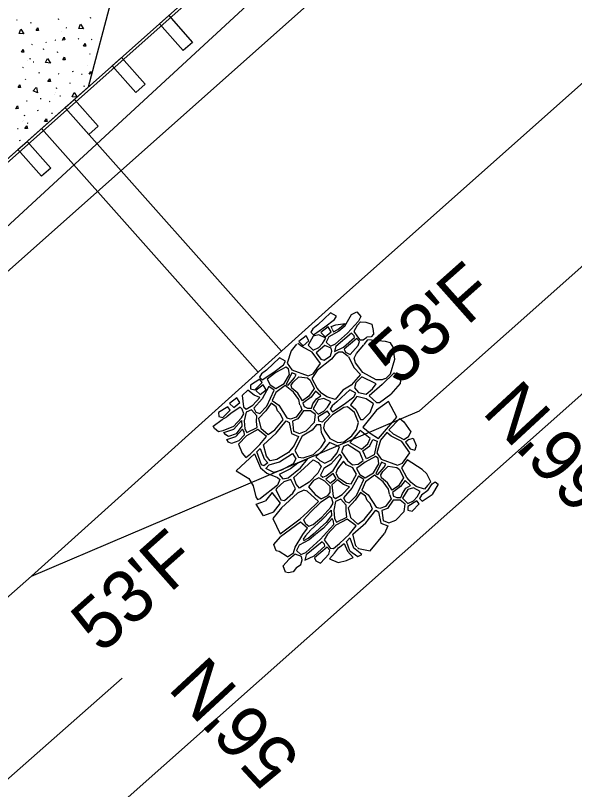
# Model space of a CAD drawing. Extents: x 49683 to 58852, y 49525 to 54803.
# Drawn here: x 53957.6 to 54010.8, y 51788.8 to 51862.4 of the extents above; entities that cross this region are included whole.
import ezdxf

# ---------------------------------------------------------------- set-up
doc = ezdxf.new("R2010")
doc.units = 0
for name, color, linetype in [('Level 11', 7, 'Continuous'), ('Level 13', 7, 'Continuous'), ('Level 16', 7, 'Continuous'), ('Level 18', 7, 'Continuous'), ('Level 27', 7, 'Continuous'), ('Level 33', 7, 'Continuous'), ('Level 48', 7, 'Continuous'), ('Level 61', 7, 'Continuous'), ('Level 8', 7, 'Continuous')]:
    doc.layers.add(name, color=color, linetype=linetype)

msp = doc.modelspace()

# ---------------------------------------------------------------- linework, layer by layer
at = {"layer": 'Level 11'}
msp.add_line((53944.235, 51830.768), (54450.301, 52297.6), dxfattribs=at)
at = {"layer": 'Level 13'}
msp.add_line((53681.554, 51593.39), (53996.93, 51873.722), dxfattribs=at)
at = {"layer": 'Level 16'}
for points in [[(53988.147, 51833.841), (53987.57, 51834.165), (53986.351, 51833.009), (53985.878, 51832.641), (53985.689, 51832.326), (53985.941, 51832.074), (53987.033, 51832.81), (53987.958, 51833.504)], [(53987.356, 51832.81), (53986.662, 51832.273), (53987.075, 51831.883), (53987.623, 51832.341)], [(53985.24, 51831.957), (53984.547, 51831.42), (53984.959, 51831.029), (53985.507, 51831.488)], [(53987.121, 51831.744), (53986.46, 51832.069), (53985.925, 51831.932), (53985.441, 51831.091), (53985.923, 51830.588), (53986.459, 51830.851), (53986.806, 51831.24)], [(53989.577, 51832.213), (53988.08, 51830.962), (53987.945, 51830.459), (53988.815, 51830.889), (53989.833, 51831.809), (53989.821, 51831.968)], [(53990.078, 51831.711), (53988.876, 51830.681), (53988.999, 51830.411), (53989.427, 51830.179), (53990.212, 51831.037), (53990.323, 51831.417)], [(53986.193, 51830.347), (53986.633, 51829.735), (53986.952, 51829.637), (53987.565, 51830.054), (53987.688, 51830.496), (53987.627, 51830.802), (53987.039, 51831.046)], [(53983.284, 51829.542), (53982.707, 51829.866), (53981.488, 51828.71), (53981.015, 51828.342), (53980.826, 51828.027), (53981.078, 51827.776), (53982.17, 51828.512), (53983.095, 51829.206)], [(53983.324, 51828.996), (53982.356, 51828.468), (53981.534, 51827.842), (53981.84, 51827.291), (53982.367, 51826.961), (53983.151, 51827.427), (53983.654, 51828.298), (53983.582, 51828.837)], [(53983.9, 51828.445), (53983.359, 51827.342), (53983.543, 51827.281), (53984.144, 51827.98), (53984.316, 51828.274)], [(53986.005, 51826.953), (53985.514, 51826.217), (53984.914, 51825.788), (53984.473, 51826.498), (53983.898, 51826.975), (53983.837, 51827.257), (53984.021, 51827.563), (53984.549, 51828.066), (53985.369, 51827.957), (53985.626, 51827.749)], [(53991.901, 51827.402), (53990.558, 51828.072), (53989.99, 51827.483), (53989.864, 51827.021), (53990.231, 51826.57), (53990.965, 51826.403), (53991.575, 51826.929)], [(53980.837, 51827.828), (53979.955, 51827.281), (53979.975, 51826.924), (53980.363, 51826.83), (53981.057, 51827.523)], [(53981.166, 51827.31), (53980.473, 51826.773), (53980.886, 51826.383), (53981.434, 51826.841)], [(53979.719, 51826.78), (53979.171, 51826.298), (53979.304, 51825.204), (53979.539, 51824.992), (53980.176, 51825.383), (53980.847, 51826.099), (53980.3, 51826.333)], [(53981.708, 51827.139), (53981.081, 51825.977), (53980.287, 51825.071), (53980.477, 51824.702), (53980.834, 51824.591), (53981.527, 51825.285), (53982.222, 51826.805)], [(53986.147, 51826.702), (53985.716, 51826.145), (53984.939, 51825.557), (53985.054, 51825.231), (53985.369, 51825.085), (53985.757, 51825.096), (53985.894, 51825.484), (53986.23, 51825.968), (53986.651, 51826.241)], [(53989.979, 51826.507), (53989.402, 51826.832), (53988.183, 51825.676), (53987.71, 51825.308), (53987.521, 51824.993), (53987.772, 51824.741), (53988.865, 51825.477), (53989.789, 51826.171)], [(53978.672, 51826.078), (53977.978, 51825.541), (53978.391, 51825.15), (53978.939, 51825.609)], [(53987.595, 51825.675), (53986.934, 51826), (53986.398, 51825.863), (53985.914, 51825.023), (53986.397, 51824.519), (53986.932, 51824.782), (53987.279, 51825.171)], [(53991.646, 51825.491), (53990.965, 51825.984), (53990.073, 51826.182), (53989.473, 51825.415), (53989.977, 51824.954), (53990.427, 51823.999), (53990.658, 51823.999), (53991.341, 51824.682)], [(53977.805, 51825.204), (53976.923, 51824.657), (53976.944, 51824.3), (53977.332, 51824.206), (53978.026, 51824.9)], [(53981.919, 51825.564), (53981.404, 51824.826), (53980.733, 51824.11), (53980.944, 51823.183), (53981.647, 51822.57), (53982.262, 51823.006), (53983.057, 51823.979), (53982.823, 51824.526), (53982.533, 51824.816), (53982.388, 51825.207)], [(53989.179, 51825.205), (53988.833, 51825.131), (53987.761, 51824.437), (53986.984, 51823.659), (53986.889, 51823.208), (53987.014, 51822.893), (53987.496, 51822.201), (53988.262, 51821.813), (53988.829, 51821.877), (53989.586, 51822.465), (53990.038, 51823.043), (53990.238, 51823.705), (53989.861, 51824.67)], [(53993.079, 51825.717), (53991.939, 51824.895), (53990.651, 51823.289), (53991.324, 51822.689), (53992.144, 51822.188), (53993.886, 51824.223)], [(53980.052, 51824.925), (53979.538, 51824.701), (53979.358, 51823.874), (53979.436, 51823.103), (53979.625, 51822.757), (53980.598, 51823.239), (53980.531, 51823.82), (53980.554, 51824.356)], [(53985.014, 51824.833), (53984.476, 51824.063), (53983.949, 51823.851), (53984.053, 51822.903), (53984.611, 51822.682), (53985.254, 51822.925), (53986.046, 51823.759), (53986.141, 51824.465), (53985.678, 51824.844)], [(53987.279, 51824.793), (53986.396, 51824.246), (53986.417, 51823.889), (53986.805, 51823.795), (53987.499, 51824.489)], [(53983.359, 51823.893), (53983.632, 51823.724), (53983.852, 51822.66), (53984.516, 51822.398), (53984.125, 51821.544), (53983.587, 51820.879), (53982.469, 51820.203), (53981.826, 51820.086), (53981.468, 51820.508), (53981.185, 51821.593), (53982.398, 51822.701)], [(53986.225, 51823.496), (53985.824, 51822.989), (53984.885, 51822.409), (53984.177, 51821.069), (53984.524, 51820.427), (53984.956, 51820.354), (53985.937, 51820.681), (53986.675, 51821.357), (53987.098, 51822.011), (53986.698, 51822.748), (53986.657, 51823.507)], [(53990.381, 51822.97), (53989.412, 51821.805), (53990.514, 51821.193), (53991.102, 51821.684), (53991.348, 51822.199)], [(53991.58, 51822.089), (53992.009, 51821.93), (53991.726, 51820.643), (53990.978, 51820.263), (53990.648, 51821.034), (53991.298, 51821.513)], [(53995.12, 51820.831), (53994.349, 51821.896), (53993.345, 51822.434), (53992.929, 51822.752), (53992.328, 51822.029), (53991.971, 51820.84), (53992.399, 51820.215), (53993.942, 51819.654), (53994.42, 51819.838)], [(53987.456, 51821.821), (53986.865, 51821.083), (53986.158, 51820.46), (53986.558, 51820.102), (53987.042, 51819.85), (53987.654, 51820.167), (53988.203, 51820.842), (53988.425, 51821.401)], [(53990.684, 51820.115), (53990.366, 51820.875), (53989.203, 51821.596), (53988.811, 51821.449), (53988.614, 51820.934), (53989.189, 51820.089), (53989.666, 51819.685), (53990.206, 51819.76)], [(53980.879, 51821.245), (53981.257, 51820.254), (53981.594, 51819.875), (53981.225, 51819.612), (53981.014, 51819.696), (53980.573, 51820.918)], [(53983.956, 51820.785), (53984.261, 51820.247), (53984.028, 51819.783), (53982.911, 51819.171), (53982.183, 51818.97), (53981.425, 51819.327), (53981.72, 51819.686), (53982.722, 51819.972)], [(53988.446, 51820.715), (53987.607, 51819.764), (53986.925, 51819.328), (53986.611, 51818.702), (53986.846, 51818.512), (53987.17, 51818.636), (53987.83, 51819.139), (53988.647, 51820.447)], [(53985.367, 51820.217), (53984.46, 51819.858), (53983.754, 51819.319), (53982.689, 51818.76), (53983.047, 51818.36), (53983.531, 51818.444), (53984.713, 51819.394)], [(53985.905, 51820.165), (53986.4, 51819.902), (53986.694, 51819.544), (53986.356, 51818.911), (53985.533, 51818.046), (53984.626, 51817.476), (53984.3, 51817.866), (53984.09, 51818.477), (53985.061, 51819.384)], [(53990.045, 51818.791), (53989.691, 51819.391), (53989.078, 51819.685), (53988.809, 51820.028), (53988.22, 51819.316), (53988.085, 51818.887), (53988.305, 51818.471), (53989.076, 51817.945), (53989.517, 51817.872)], [(53991.836, 51820.484), (53990.867, 51819.956), (53990.046, 51819.331), (53990.352, 51818.78), (53990.878, 51818.449), (53991.663, 51818.916), (53992.166, 51819.786), (53992.093, 51820.325)], [(53992.411, 51819.934), (53991.871, 51818.83), (53992.055, 51818.769), (53992.656, 51819.468), (53992.828, 51819.763)], [(53994.517, 51818.441), (53994.026, 51817.706), (53993.425, 51817.276), (53992.985, 51817.986), (53992.409, 51818.463), (53992.349, 51818.745), (53992.533, 51819.052), (53993.06, 51819.555), (53993.881, 51819.445), (53994.138, 51819.237)], [(53987.548, 51817.049), (53987.526, 51817.63), (53987.024, 51818.133), (53986.466, 51818.467), (53985.94, 51818.187), (53985.47, 51817.583), (53986.095, 51816.869), (53986.676, 51816.445), (53987.313, 51816.77)], [(53987.829, 51818.871), (53987.136, 51818.334), (53987.549, 51817.943), (53988.097, 51818.402)], [(53990.22, 51818.628), (53989.593, 51817.465), (53988.799, 51816.559), (53988.988, 51816.191), (53989.345, 51816.08), (53990.039, 51816.773), (53990.733, 51818.293)], [(53983.784, 51818.297), (53983.131, 51818.086), (53982.466, 51817.484), (53982.381, 51817.337), (53982.844, 51816.367), (53983.181, 51816.284), (53983.994, 51816.991), (53984.236, 51817.423)], [(53988.231, 51818.268), (53987.683, 51817.787), (53987.816, 51816.692), (53988.05, 51816.48), (53988.687, 51816.872), (53989.358, 51817.588), (53988.811, 51817.822)], [(53994.659, 51818.191), (53994.228, 51817.634), (53993.45, 51817.045), (53993.565, 51816.72), (53993.88, 51816.573), (53994.269, 51816.584), (53994.405, 51816.973), (53994.742, 51817.456), (53995.162, 51817.73)], [(53990.43, 51817.053), (53989.916, 51816.315), (53989.244, 51815.599), (53989.456, 51814.672), (53990.159, 51814.058), (53990.774, 51814.495), (53991.568, 51815.468), (53991.334, 51816.015), (53991.044, 51816.305), (53990.899, 51816.696)], [(53996.106, 51817.164), (53995.445, 51817.488), (53994.91, 51817.351), (53994.426, 51816.511), (53994.908, 51816.008), (53995.444, 51816.271), (53995.791, 51816.66)], [(53987.48, 51816.67), (53986.597, 51816.076), (53985.691, 51815.215), (53984.986, 51814.443), (53985.198, 51814.097), (53985.5, 51813.841), (53985.913, 51814.009), (53986.752, 51814.714), (53987.602, 51815.653), (53987.826, 51816.033), (53987.681, 51816.491)], [(53988.564, 51816.414), (53988.05, 51816.19), (53987.87, 51815.363), (53987.947, 51814.592), (53988.137, 51814.246), (53989.109, 51814.727), (53989.043, 51815.308), (53989.066, 51815.845)], [(53993.526, 51816.321), (53992.987, 51815.551), (53992.46, 51815.34), (53992.564, 51814.391), (53993.123, 51814.171), (53993.766, 51814.414), (53994.557, 51815.247), (53994.653, 51815.954), (53994.19, 51816.332)], [(53995.79, 51816.282), (53994.908, 51815.735), (53994.929, 51815.378), (53995.317, 51815.284), (53996.01, 51815.977)], [(53989.991, 51813.89), (53989.165, 51814.537), (53988.081, 51813.944), (53987.275, 51813.094), (53986.973, 51812.546), (53987.33, 51812.033), (53987.542, 51811.754), (53987.855, 51811.732), (53988.436, 51812.202), (53989.364, 51813.108)], [(53986.759, 51812.372), (53985.263, 51811.121), (53985.128, 51810.619), (53985.998, 51811.048), (53987.016, 51811.968), (53987.004, 51812.128)]]:
    msp.add_lwpolyline(points, close=True, dxfattribs=at)
for points in [[(53988.938, 51832.881), (53989.572, 51833.997), (53990.08, 51834.244), (53990.463, 51833.819), (53990.243, 51833.346), (53989.182, 51832.231)], [(53987.738, 51832.625), (53987.689, 51832.721), (53987.632, 51832.84), (53988.06, 51832.997), (53988.963, 51833.13)], [(53987.738, 51832.596), (53987.8, 51832.468), (53987.849, 51832.346), (53988.254, 51832.555), (53988.963, 51833.13)], [(53988.924, 51833.105), (53988.855, 51833.045)], [(53990.427, 51833.288), (53990.093, 51832.935), (53989.79, 51832.387), (53990.147, 51831.873), (53990.359, 51831.594), (53990.672, 51831.572), (53991.009, 51831.844)], [(53990.427, 51833.288), (53990.914, 51833.265), (53991.511, 51833.08), (53991.61, 51832.463), (53991.651, 51832.115), (53991.44, 51831.882), (53991.009, 51831.844)], [(53988.938, 51832.881), (53988.364, 51832.395), (53987.408, 51831.88), (53987.15, 51831.377), (53987.566, 51830.985), (53988.044, 51831.194), (53989.182, 51832.231)], [(53984.349, 51831.182), (53983.816, 51830.54), (53983.46, 51829.351), (53983.888, 51828.727), (53985.431, 51828.165), (53985.909, 51828.349), (53986.608, 51829.343), (53985.838, 51830.408), (53984.834, 51830.946), (53984.462, 51831.229)], [(53992.668, 51827.866), (53992.489, 51827.78), (53991.901, 51827.78), (53990.642, 51828.471), (53989.929, 51829.394), (53989.814, 51829.845), (53990.046, 51830.286), (53990.748, 51831.121)], [(53990.764, 51831.136), (53991.12, 51831.583)], [(53992.668, 51827.866), (53992.872, 51827.941), (53993.284, 51828.36), (53993.673, 51829.743), (53993.513, 51830.898), (53993.272, 51831.296), (53992.795, 51831.44), (53991.12, 51831.583)], [(53989.257, 51830.011), (53988.717, 51830.423), (53988.362, 51830.41), (53988.006, 51830.202), (53987.663, 51829.76), (53986.314, 51828.656), (53985.798, 51827.92), (53986.275, 51827.025)], [(53989.283, 51829.985), (53989.771, 51828.963), (53990.421, 51828.292), (53989.518, 51827.263), (53988.73, 51826.81), (53988.004, 51825.896), (53987.207, 51826.147), (53986.724, 51826.525), (53986.301, 51826.999)], [(53992.466, 51827.326), (53993.633, 51828.459), (53994.223, 51827.715), (53994.198, 51827.422), (53993.304, 51826.413)], [(53984.658, 51825.402), (53984.558, 51825.897), (53984.057, 51826.595), (53983.249, 51827.231), (53982.378, 51826.581), (53982.022, 51825.809), (53982.646, 51825.356), (53983.409, 51824.166)], [(53992.466, 51827.326), (53991.238, 51826.257), (53991.93, 51825.607), (53992.224, 51825.607), (53993.304, 51826.413)], [(53978.353, 51823.35), (53979.091, 51824.165), (53979.315, 51824.545), (53979.17, 51825.003), (53978.969, 51825.181), (53978.086, 51824.588), (53977.723, 51824.243)], [(53984.673, 51825.375), (53984.835, 51824.969), (53984.297, 51824.242), (53983.759, 51824.041), (53983.436, 51824.137)], [(53978.353, 51823.35), (53977.339, 51822.928), (53976.906, 51822.844), (53976.523, 51823.134), (53976.422, 51823.383), (53977.277, 51824.017), (53977.723, 51824.243)], [(53978.367, 51823.093), (53979.113, 51823.896), (53979.146, 51823.371), (53978.6, 51822.656)], [(53993.124, 51823.023), (53994.167, 51824.085), (53994.546, 51823.783), (53995.197, 51822.822), (53994.963, 51822.356)], [(53978.6, 51822.656), (53977.88, 51822.384), (53977.614, 51822.531), (53977.433, 51822.763), (53978.367, 51823.093)], [(53978.859, 51821.981), (53979.379, 51822.534), (53979.346, 51822.835), (53979.201, 51823.092), (53978.578, 51822.401)], [(53979.517, 51820.384), (53979.925, 51820.713), (53980.853, 51821.619), (53981.48, 51822.402), (53980.653, 51823.049), (53979.569, 51822.456), (53978.822, 51821.667)], [(53993.124, 51823.023), (53993.517, 51822.63), (53994.545, 51822.092), (53994.983, 51822.378)], [(53978.859, 51821.981), (53978.149, 51821.713), (53977.883, 51821.859), (53977.701, 51822.091), (53978.578, 51822.401)], [(53995.03, 51822.104), (53994.704, 51821.835), (53995.145, 51821.223), (53995.59, 51821.087)], [(53995.03, 51822.104), (53995.432, 51822.235), (53995.713, 51821.536), (53995.59, 51821.087)], [(53978.822, 51821.667), (53979.157, 51820.789), (53979.517, 51820.384)], [(53980.354, 51820.747), (53978.583, 51819.128), (53979.803, 51818.398), (53980.218, 51817.706), (53980.459, 51816.645), (53980.635, 51816.405), (53980.911, 51816.477)], [(53980.354, 51820.747), (53980.898, 51819.411), (53981.519, 51818.895), (53982.53, 51818.496), (53982.741, 51818.285), (53982.519, 51817.769), (53980.911, 51816.477)], [(53994.844, 51820.171), (53994.31, 51819.409), (53994.786, 51818.514)], [(53996.799, 51817.741), (53997.107, 51818.077), (53996.735, 51818.826), (53996.287, 51819.243), (53994.844, 51820.171)], [(53993.169, 51816.891), (53993.07, 51817.386), (53992.568, 51818.084), (53991.76, 51818.72), (53990.89, 51818.07), (53990.534, 51817.297), (53991.158, 51816.845), (53991.92, 51815.655)], [(53996.799, 51817.741), (53996.516, 51817.385), (53995.718, 51817.636), (53995.236, 51818.013), (53994.813, 51818.487)], [(53996.808, 51817.253), (53997.22, 51817.871), (53997.521, 51818.083), (53997.79, 51817.851), (53997.226, 51816.865)], [(53982.158, 51815.189), (53982.828, 51816.044), (53982.032, 51817.051), (53981.383, 51816.269)], [(53984.687, 51814.556), (53985.378, 51815.192), (53986.418, 51816.21), (53985.347, 51817.192), (53985.034, 51817.281), (53984.431, 51816.99), (53983.292, 51815.951)], [(53996.808, 51817.253), (53996.221, 51816.797), (53996.032, 51816.481), (53996.284, 51816.23), (53997.226, 51816.865)], [(53982.158, 51815.189), (53981.19, 51814.853), (53980.497, 51815.934), (53981.383, 51816.269)], [(53993.184, 51816.864), (53993.347, 51816.458), (53992.808, 51815.73), (53992.271, 51815.529), (53991.947, 51815.626)], [(53983.275, 51815.934), (53982.903, 51815.615), (53982.069, 51814.585), (53982.778, 51813.115), (53984.669, 51814.539)], [(53985.717, 51813.544), (53986.752, 51814.445), (53987.624, 51815.385), (53987.657, 51814.86), (53987.154, 51814.2), (53986.628, 51813.719), (53986.038, 51813.204)], [(53990.069, 51811.891), (53989.98, 51811.996), (53989.696, 51813.081), (53990.91, 51814.189), (53991.87, 51815.381), (53992.144, 51815.213), (53992.364, 51814.149), (53993.028, 51813.886), (53992.692, 51813.154)], [(53983.488, 51810.941), (53984.063, 51811.316), (53984.198, 51811.843), (53984.947, 51813.056), (53985.376, 51813.657), (53984.715, 51814.245), (53982.82, 51812.831)], [(53986.629, 51812.633), (53987.175, 51813.262), (53987.891, 51814.022), (53987.858, 51814.324), (53987.713, 51814.581), (53986.896, 51813.675), (53986.173, 51813.088)], [(53985.692, 51813.519), (53985.179, 51812.922), (53984.983, 51812.628), (53985.032, 51812.505), (53985.436, 51812.714), (53986.019, 51813.187)], [(53983.488, 51810.941), (53982.696, 51811.434), (53982.393, 51811.507), (53982.17, 51812.103), (53982.82, 51812.831)], [(53986.148, 51813.063), (53985.546, 51812.555), (53984.59, 51812.039), (53984.332, 51811.537), (53984.748, 51811.145), (53985.226, 51811.354), (53986.603, 51812.608)], [(53989.403, 51811.523), (53989.084, 51812.406), (53989.39, 51812.733), (53989.754, 51811.781)], [(53990.132, 51811.831), (53990.241, 51811.747), (53991.339, 51811.517), (53992.692, 51813.154)], [(53986.61, 51810.338), (53987.395, 51811.197), (53987.506, 51811.577), (53987.261, 51811.871), (53986.059, 51810.84), (53986.181, 51810.571), (53986.61, 51810.338)], [(53987.946, 51811.296), (53988.335, 51811.784), (53988.873, 51812.216), (53989.175, 51811.475)], [(53989.403, 51811.523), (53990.151, 51810.956), (53990.554, 51811.151), (53989.754, 51811.781)], [(53984.331, 51809.931), (53984.747, 51810.214), (53984.87, 51810.655), (53984.809, 51810.961), (53984.222, 51811.206), (53983.599, 51810.691)], [(53987.48, 51810.745), (53987.931, 51811.281)], [(53988.287, 51810.394), (53989.094, 51810.584), (53989.716, 51810.885), (53989.175, 51811.475)], [(53984.331, 51809.931), (53984.032, 51809.525), (53983.587, 51809.419), (53983.283, 51809.491), (53983.061, 51810.088), (53983.599, 51810.691)], [(53987.48, 51810.745), (53988.287, 51810.394)]]:
    msp.add_lwpolyline(points, dxfattribs=at)
at = {"layer": 'Level 18'}
for p, q in [((53987.374, 51834.526), (54024.727, 51867.764)), ((53996.042, 51824.838), (54033.388, 51858.07)), ((53959.122, 51809.112), (53987.374, 51834.526)), ((53959.122, 51809.112), (53996.042, 51824.838)), ((53955.241, 51805.689), (53959.122, 51809.112))]:
    msp.add_line(p, q, dxfattribs=at)
at = {"layer": 'Level 27'}
for p, q in [((53938.412, 51832.41), (54196.384, 52061.717)), ((53938.578, 51832.223), (54196.55, 52061.53)), ((53971.298, 51861.642), (53972.182, 51862.427)), ((53972.182, 51862.427), (53974.44, 51859.886)), ((53973.557, 51859.101), (53971.298, 51861.642)), ((53974.44, 51859.886), (53973.557, 51859.101)), ((53966.814, 51857.656), (53967.698, 51858.441)), ((53967.698, 51858.441), (53969.956, 51855.9)), ((53969.072, 51855.115), (53966.814, 51857.656)), ((53969.956, 51855.9), (53969.072, 51855.115)), ((53962.329, 51853.67), (53963.213, 51854.455)), ((53963.213, 51854.455), (53965.472, 51851.913)), ((53964.588, 51851.128), (53962.329, 51853.67)), ((53965.472, 51851.913), (53964.588, 51851.128)), ((53957.845, 51849.684), (53958.729, 51850.469)), ((53958.729, 51850.469), (53960.987, 51847.927)), ((53960.103, 51847.142), (53957.845, 51849.684)), ((53960.987, 51847.927), (53960.103, 51847.142))]:
    msp.add_line(p, q, dxfattribs=at)
at = {"layer": 'Level 33'}
msp.add_line((53814.147, 51651.041), (54231.595, 52022.104), dxfattribs=at)
at = {"layer": 'Level 61'}
msp.add_line((53517.816, 51402.461), (53967.758, 51799.396), dxfattribs=at)
at = {"layer": 'Level 8'}
for p, q in [((53964.572, 51855.663), (53969.139, 51873.103)), ((53957.721, 51862.077), (53957.747, 51861.99)), ((53961.668, 51862.147), (53961.693, 51862.059)), ((53964.731, 51862.273), (53964.757, 51862.186)), ((53959.057, 51861.803), (53959.083, 51861.716)), ((53962.511, 51861.251), (53962.447, 51861.269)), ((53961.971, 51860.897), (53961.971, 51860.897)), ((53959.241, 51859.655), (53959.177, 51859.674)), ((53960.506, 51859.952), (53960.531, 51859.864)), ((53961.437, 51860.063), (53961.373, 51860.081)), ((53963.629, 51860.197), (53963.568, 51860.255)), ((53964.916, 51860.125), (53964.852, 51860.144)), ((53960.246, 51859.291), (53960.272, 51859.203)), ((53961.582, 51859.017), (53961.608, 51858.929)), ((53958.793, 51858.202), (53958.793, 51858.202)), ((53958.92, 51858.31), (53958.92, 51858.31)), ((53958.971, 51858.372), (53958.997, 51858.284)), ((53964.646, 51858.842), (53964.672, 51858.754)), ((53958.386, 51857.476), (53958.322, 51857.494)), ((53959.361, 51857.994), (53959.297, 51858.013)), ((53964.496, 51857.657), (53964.496, 51857.657)), ((53959.849, 51857.05), (53959.875, 51856.962)), ((53961.766, 51856.868), (53961.702, 51856.887)), ((53963.031, 51857.165), (53963.057, 51857.077)), ((53963.962, 51856.822), (53963.898, 51856.841)), ((53958.531, 51856.43), (53958.557, 51856.342)), ((53962.771, 51856.05), (53962.797, 51855.963)), ((53953.361, 51845.698), (53964.572, 51855.663)), ((53961.497, 51855.585), (53961.522, 51855.497)), ((53964.107, 51855.776), (53964.133, 51855.689)), ((53959.98, 51854.578), (53960.006, 51854.49)), ((53961.318, 51854.962), (53961.318, 51854.962)), ((53961.445, 51855.07), (53961.445, 51855.07)), ((53961.886, 51854.754), (53961.822, 51854.772)), ((53958.715, 51854.281), (53958.651, 51854.3)), ((53960.911, 51854.235), (53960.847, 51854.254)), ((53962.374, 51853.809), (53962.4, 51853.722)), ((53958.446, 51852.998), (53958.471, 51852.91)), ((53959.72, 51853.463), (53959.746, 51853.376)), ((53961.056, 51853.189), (53961.082, 51853.102)), ((53962.329, 51853.67), (53982.913, 51830.514)), ((53958.267, 51852.375), (53958.267, 51852.375)), ((53958.394, 51852.483), (53958.394, 51852.483)), ((53957.86, 51851.648), (53957.796, 51851.667)), ((53958.836, 51852.167), (53958.772, 51852.185)), ((53960.087, 51851.677), (53980.682, 51828.507)), ((53958.006, 51850.602), (53958.031, 51850.515))]:
    msp.add_line(p, q, dxfattribs=at)
for points in [[(53958.137, 51861.148), (53958.423, 51860.698), (53957.949, 51860.745), (53958.132, 51861.141)], [(53959.75, 51861.269), (53959.815, 51861.021), (53959.584, 51861.007), (53959.75, 51861.269)], [(53963.811, 51861.618), (53964.097, 51861.168), (53963.623, 51861.215), (53963.807, 51861.61)], [(53962.257, 51860.365), (53962.322, 51860.117), (53962.092, 51860.103), (53962.257, 51860.365)], [(53964.253, 51859.786), (53964.318, 51859.538), (53964.087, 51859.524), (53964.253, 51859.786)], [(53958.345, 51859.21), (53958.41, 51858.962), (53958.179, 51858.949), (53958.345, 51859.21)], [(53960.662, 51858.362), (53960.948, 51857.911), (53960.474, 51857.958), (53960.657, 51858.354)], [(53962.275, 51858.482), (53962.34, 51858.234), (53962.109, 51858.22), (53962.275, 51858.482)], [(53964.783, 51857.125), (53964.847, 51856.877), (53964.617, 51856.863), (53964.783, 51857.125)], [(53960.87, 51856.424), (53960.935, 51856.176), (53960.704, 51856.162), (53960.87, 51856.424)], [(53958.023, 51855.85), (53958.088, 51855.602), (53957.857, 51855.588), (53958.023, 51855.85)], [(53959.597, 51855.598), (53959.712, 51855.077), (53959.283, 51855.283), (53959.59, 51855.592)], [(53963.187, 51855.121), (53963.473, 51854.671), (53962.999, 51854.717), (53963.182, 51855.113)], [(53957.819, 51853.837), (53957.884, 51853.589), (53957.653, 51853.575), (53957.819, 51853.837)], [(53960.548, 51852.61), (53960.613, 51852.362), (53960.382, 51852.348), (53960.548, 51852.61)], [(53958.681, 51851.951), (53958.746, 51851.703), (53958.515, 51851.689), (53958.681, 51851.951)]]:
    msp.add_lwpolyline(points, dxfattribs=at)

# ---------------------------------------------------------------- texts
at = {"layer": 'Level 48'}
for s, rotation, p in [("53'F", 41.63339, (53994.017, 51827.052)), ("66'N", 132.85283, (54014.752, 51818.142)), ("53'F", 41.63338, (53965.765, 51801.638)), ("56'N", 132.85283, (53984.873, 51791.849))]:
    msp.add_text(s, height=5, rotation=rotation, dxfattribs=at).set_placement(p)

doc.saveas('drawing.dxf')
